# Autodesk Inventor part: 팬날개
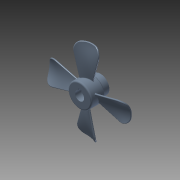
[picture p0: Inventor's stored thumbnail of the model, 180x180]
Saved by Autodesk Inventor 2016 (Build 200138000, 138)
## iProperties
Company: 한국ATC센터
Created: 2016-06
Part Number: 팬날개
Document SubType Name: Modeling
Designer: mdu
Density: 1.06 g/cm^3
Material: ABS 플라스틱
Mass: 29.2288 g
Surface Area: 148.227 cm^2
Volume: 27.5744 cm^3
Appearance: 강청색
Author: mdu
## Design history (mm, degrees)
sketch "스케치1"
  geometry: L1 (-15, 0)-(15, 0); L2 (-15, 0)-(-15, 17); L3 (-15, 17)-(5, 17); L4 (5, 17)-(5, 13); L5 (5, 13)-(15, 13); L6 (15, 13)-(15, 0); 2 further points
  constraints: 12 end point, 3 parallel, 2 perpendicular, 1 coincident, 1 horizontal, 1 midpoint
  dimensions: "d0" = 30 distance of L1.start L1.end; "d8" = 34 diameter of L3 L1; "d10" = 26 diameter of L5 L1; "d32" = 20 distance of L2.end L3.end
revolve "회전1" sketch "스케치1" stored, may be unused: angle "d11" = 90 deg
node "작업 평면2"
sketch "스케치7"
  geometry: L1 (-15, 17)-(5, 17) reference; L2 (-15, -17)-(5, -17) reference; L3 (-5, 17)-(-5, -17); A1 r 35 centre (-36.399, -13.457) between (-2, -7) and (-8, 7); 1 further point
  constraints: 2 end point, 2 midpoint, 2 point on circle, 1 centre point
  dimensions: "d36" = 35 radius of A1; "d37" = 10 distance from line of A1.start L2; "d38" = 10 distance from line of A1.end L1; "d45" = 3 distance from line of A1.end L3; "d46" = 3 distance from line of A1.start L3
sketch "3D 스케치1"
  geometry: L1 through (0, 0) direction (1, 0) reference; L2 through (0, 0) direction (1, 0) reference; 13 other entities
  constraints: 2 collinear
  node "투영 원본 위치 스케치7"
sketch "스케치8"
  geometry: L1 (-15, 17)-(5, 17) reference; L2 (-15, -17)-(5, -17) reference; L3 (-5, 17)-(-5, -17); A1 r 30 centre (-28.74, -3.591) between (-3, -19) and (-9, 19); 1 further point
  constraints: 2 end point, 2 midpoint, 2 point on circle, 1 centre point
  dimensions: "d43" = 30 radius of A1; "d47" = 4 distance from line of A1.end L3; "d48" = 2 distance from line of A1.start L3; "d58" = 2 distance from line of A1.end L1; "d59" = 2 distance from line of A1.start L2
sketch "3D 스케치2"
sketch "3D 스케치3"
feature "경계 패치1" sketch "3D 스케치2", "3D 스케치3" dims "d50" = 0
feature "연장1" dims "d55" = 2
feature "두껍게 하기1" dims "d51" = 2, "d52" = 2
sketch "스케치9"
  geometry: C1 r 59 at (0, 0); 1 further point
  constraints: 1 centre point, 1 coincident
  dimensions: "d60" = 118 diameter of C1
extrude "돌출2" sketch "스케치9" distance "d62" = 200; taper "d63" = 0 deg
fillet "모깎기6" dims "d64" = 10
fillet "모깎기7" dims "d66" = 0.8
fillet "모깎기8" dims "d67" = 0.8
sketch "스케치2"
  geometry: L1 (-2.5, 6)-(-2.5, 8.8); L2 (-2.5, 8.8)-(2.5, 8.8); L3 (2.5, 8.8)-(2.5, 6); A1 r 6.5 centre (0, 0) between (-2.5, 6) and (2.5, 6); 1 further point
  constraints: 6 end point, 2 parallel, 2 point on circle, 1 centre point, 1 coincident, 1 horizontal, 1 vertical
  dimensions: "d12" = 13 diameter of A1; "d13" = 5 distance of L1.end L2.end; "d14" = 15.3 dimension on A1 L2 (computed from d12)
extrude "돌출1" cut sketch "스케치2" stored distance "d15" = 10; taper "d16" = 0 deg
chamfer "모따기1" distance "d17" = 1; stored, may be unused: second distance "d18" = 2, angle "d19" = 45 deg
node "작업 평면1"
sketch "스케치3"
  geometry: L1 (5, -13)-(5, 13) reference; 3 further points
  constraints: 1 horizontal alignment, 1 midpoint
  dimensions: "d20" = 5 distance from line of L1 point (0, 0)
hole "구멍1" sketch "스케치3" at (0, 0) diameter "d21" = 3.242; stored, may be unused: countersink angle "d25" = 90 deg, drill point angle "d27" = 118 deg; dims "d22" = 6, "d23" = 4, "d24" = 2, "d26" = 8
fillet "모깎기9" dims "d77" = 2
fillet "모깎기10" dims "d78" = 2
fillet "모깎기11" dims "d79" = 2
node "솔리드1"
pattern_circular "원형 패턴1" dims "d69" = 360 deg
pattern_circular "원형 패턴2" dims angle "d72" = 360 deg
pattern_circular "원형 패턴3" dims angle "d75" = 360 deg
node "투영 원본 위치 스케치8"
node "곡면1"
node "곡면2"
node "곡면3"
node "곡면4"
feature "경계 패치2"
feature "경계 패치3"
feature "경계 패치4"
